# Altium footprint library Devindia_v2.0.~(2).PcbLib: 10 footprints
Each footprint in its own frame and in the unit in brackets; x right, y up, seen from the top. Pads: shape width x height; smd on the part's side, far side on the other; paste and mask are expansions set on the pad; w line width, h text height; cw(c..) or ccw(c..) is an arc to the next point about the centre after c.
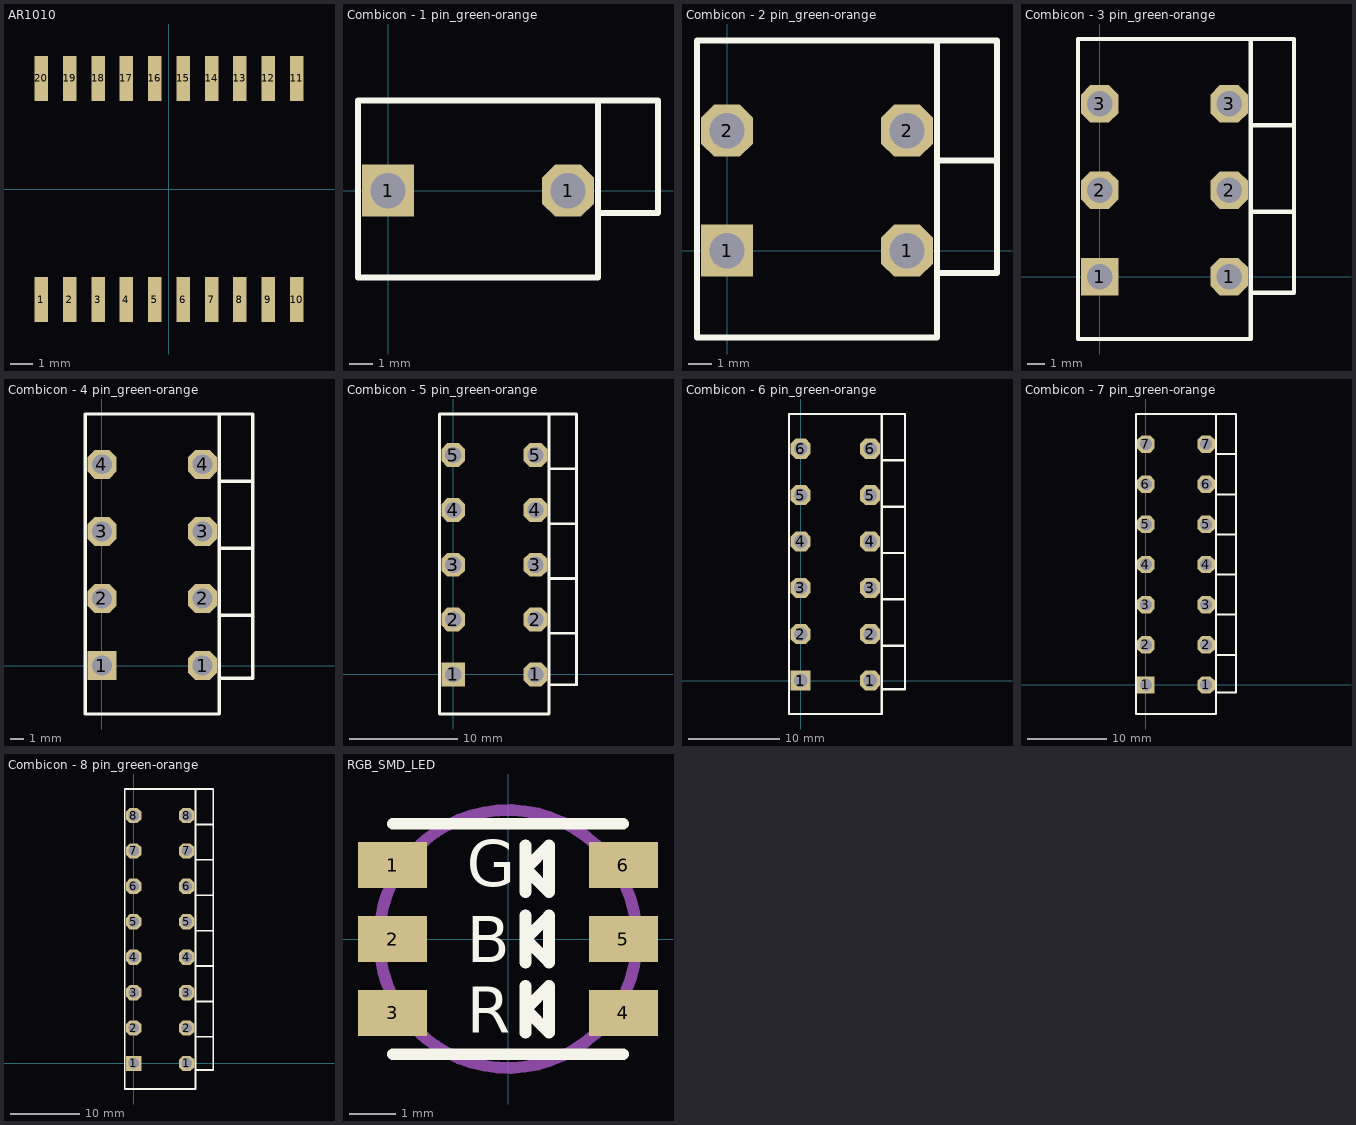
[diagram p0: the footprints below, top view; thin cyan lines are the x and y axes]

## AR1010 [mm]
pads (20):
  rect 0.6x2 smd: 1(-5.715,-4.95) 2(-4.445,-4.95) 3(-3.175,-4.95) 4(-1.905,-4.95) 5(-0.635,-4.95) 6(0.635,-4.95) 7(1.905,-4.95) 8(3.175,-4.95) 9(4.445,-4.95) 10(5.715,-4.95) 11(5.715,4.95) 12(4.445,4.95) 13(3.175,4.95) 14(1.905,4.95) 15(0.635,4.95) 16(-0.635,4.95) 17(-1.905,4.95) 18(-3.175,4.95) 19(-4.445,4.95) 20(-5.715,4.95)
Bottom Overlay:
  circle w0.254: c-5.695,-3.115 r0.284
  lines w0.254: -6.4,-3.75 -6.4,3.75 6.4,3.75 6.4,-3.75 -6.4,-3.75
3D body: height 2.15, standoff 2.05, extent -5.969,-2.54 -5.46,-2.034
3D body: height 0.32, standoff 0, extent -5.969,-5.588 -5.461,-4.318
3D body: height 1, standoff 0.16, extent -5.969,-4.445 -5.461,-4.191
3D body: height 0.32, standoff 0, extent -5.969,-4.51 -5.461,-4.191
3D body: height 1.16, standoff 0.84, extent -5.969,-4.445 -5.461,-4.126
3D body: height 1.16, standoff 0.84, extent -5.969,-4.318 -5.461,-3.175
3D body: height 0.32, standoff 0, extent -4.699,-5.588 -4.191,-4.318
3D body: height 1, standoff 0.16, extent -4.699,-4.445 -4.191,-4.191
3D body: height 0.32, standoff 0, extent -4.699,-4.51 -4.191,-4.191
3D body: height 1.16, standoff 0.84, extent -4.699,-4.445 -4.191,-4.126
3D body: height 1.16, standoff 0.84, extent -4.699,-4.318 -4.191,-3.175
3D body: height 0.32, standoff 0, extent -3.429,-5.588 -2.921,-4.318
3D body: height 1, standoff 0.16, extent -3.429,-4.445 -2.921,-4.191
3D body: height 0.32, standoff 0, extent -3.429,-4.51 -2.921,-4.191
3D body: height 1.16, standoff 0.84, extent -3.429,-4.445 -2.921,-4.126
3D body: height 1.16, standoff 0.84, extent -3.429,-4.318 -2.921,-3.175
3D body: height 0.32, standoff 0, extent -2.159,-5.588 -1.651,-4.318
3D body: height 1, standoff 0.16, extent -2.159,-4.445 -1.651,-4.191
3D body: height 0.32, standoff 0, extent -2.159,-4.51 -1.651,-4.191
3D body: height 1.16, standoff 0.84, extent -2.159,-4.445 -1.651,-4.126
3D body: height 1.16, standoff 0.84, extent -2.159,-4.318 -1.651,-3.175
3D body: height 0.32, standoff 0, extent -0.889,-5.588 -0.381,-4.318
3D body: height 1, standoff 0.16, extent -0.889,-4.445 -0.381,-4.191
3D body: height 0.32, standoff 0, extent -0.889,-4.51 -0.381,-4.191
3D body: height 1.16, standoff 0.84, extent -0.889,-4.445 -0.381,-4.126
3D body: height 1.16, standoff 0.84, extent -0.889,-4.318 -0.381,-3.175
3D body: height 0.32, standoff 0, extent 0.381,-5.588 0.889,-4.318
3D body: height 1, standoff 0.16, extent 0.381,-4.445 0.889,-4.191
3D body: height 0.32, standoff 0, extent 0.381,-4.51 0.889,-4.191
3D body: height 1.16, standoff 0.84, extent 0.381,-4.445 0.889,-4.126
3D body: height 1.16, standoff 0.84, extent 0.381,-4.318 0.889,-3.175
3D body: height 0.32, standoff 0, extent 1.651,-5.588 2.159,-4.318
3D body: height 1, standoff 0.16, extent 1.651,-4.445 2.159,-4.191
3D body: height 0.32, standoff 0, extent 1.651,-4.51 2.159,-4.191
3D body: height 1.16, standoff 0.84, extent 1.651,-4.445 2.159,-4.126
3D body: height 1.16, standoff 0.84, extent 1.651,-4.318 2.159,-3.175
3D body: height 0.32, standoff 0, extent 2.921,-5.588 3.429,-4.318
3D body: height 1, standoff 0.16, extent 2.921,-4.445 3.429,-4.191
3D body: height 0.32, standoff 0, extent 2.921,-4.51 3.429,-4.191
3D body: height 1.16, standoff 0.84, extent 2.921,-4.445 3.429,-4.126
3D body: height 1.16, standoff 0.84, extent 2.921,-4.318 3.429,-3.175
3D body: height 0.32, standoff 0, extent 4.191,-5.588 4.699,-4.318
3D body: height 1, standoff 0.16, extent 4.191,-4.445 4.699,-4.191
3D body: height 0.32, standoff 0, extent 4.191,-4.51 4.699,-4.191
3D body: height 1.16, standoff 0.84, extent 4.191,-4.445 4.699,-4.126
3D body: height 1.16, standoff 0.84, extent 4.191,-4.318 4.699,-3.175
3D body: height 0.32, standoff 0, extent 5.461,-5.588 5.969,-4.318
3D body: height 1, standoff 0.16, extent 5.461,-4.445 5.969,-4.191
3D body: height 0.32, standoff 0, extent 5.461,-4.51 5.969,-4.191
3D body: height 1.16, standoff 0.84, extent 5.461,-4.445 5.969,-4.126
3D body: height 1.16, standoff 0.84, extent 5.461,-4.318 5.969,-3.175
3D body: height 0.32, standoff 0, extent 5.461,4.318 5.969,5.588
3D body: height 1, standoff 0.16, extent 5.461,4.191 5.969,4.445
3D body: height 0.32, standoff 0, extent 5.461,4.191 5.969,4.51
3D body: height 1.16, standoff 0.84, extent 5.461,4.126 5.969,4.445
3D body: height 1.16, standoff 0.84, extent 5.461,3.175 5.969,4.318
3D body: height 0.32, standoff 0, extent 4.191,4.318 4.699,5.588
3D body: height 1, standoff 0.16, extent 4.191,4.191 4.699,4.445
3D body: height 0.32, standoff 0, extent 4.191,4.191 4.699,4.51
3D body: height 1.16, standoff 0.84, extent 4.191,4.126 4.699,4.445
3D body: height 1.16, standoff 0.84, extent 4.191,3.175 4.699,4.318
3D body: height 0.32, standoff 0, extent 2.921,4.318 3.429,5.588
3D body: height 1, standoff 0.16, extent 2.921,4.191 3.429,4.445
3D body: height 0.32, standoff 0, extent 2.921,4.191 3.429,4.51
3D body: height 1.16, standoff 0.84, extent 2.921,4.126 3.429,4.445
3D body: height 1.16, standoff 0.84, extent 2.921,3.175 3.429,4.318
3D body: height 0.32, standoff 0, extent 1.651,4.318 2.159,5.588
3D body: height 1, standoff 0.16, extent 1.651,4.191 2.159,4.445
3D body: height 0.32, standoff 0, extent 1.651,4.191 2.159,4.51
3D body: height 1.16, standoff 0.84, extent 1.651,4.126 2.159,4.445
3D body: height 1.16, standoff 0.84, extent 1.651,3.175 2.159,4.318
3D body: height 0.32, standoff 0, extent 0.381,4.318 0.889,5.588
3D body: height 1, standoff 0.16, extent 0.381,4.191 0.889,4.445
3D body: height 0.32, standoff 0, extent 0.381,4.191 0.889,4.51
3D body: height 1.16, standoff 0.84, extent 0.381,4.126 0.889,4.445
3D body: height 1.16, standoff 0.84, extent 0.381,3.175 0.889,4.318
3D body: height 0.32, standoff 0, extent -0.889,4.318 -0.381,5.588
3D body: height 1, standoff 0.16, extent -0.889,4.191 -0.381,4.445
3D body: height 0.32, standoff 0, extent -0.889,4.191 -0.381,4.51
3D body: height 1.16, standoff 0.84, extent -0.889,4.126 -0.381,4.445
3D body: height 1.16, standoff 0.84, extent -0.889,3.175 -0.381,4.318
3D body: height 0.32, standoff 0, extent -2.159,4.318 -1.651,5.588
3D body: height 1, standoff 0.16, extent -2.159,4.191 -1.651,4.445
3D body: height 0.32, standoff 0, extent -2.159,4.191 -1.651,4.51
3D body: height 1.16, standoff 0.84, extent -2.159,4.126 -1.651,4.445
3D body: height 1.16, standoff 0.84, extent -2.159,3.175 -1.651,4.318
3D body: height 0.32, standoff 0, extent -3.429,4.318 -2.921,5.588
3D body: height 1, standoff 0.16, extent -3.429,4.191 -2.921,4.445
3D body: height 0.32, standoff 0, extent -3.429,4.191 -2.921,4.51
3D body: height 1.16, standoff 0.84, extent -3.429,4.126 -2.921,4.445
3D body: height 1.16, standoff 0.84, extent -3.429,3.175 -2.921,4.318
3D body: height 0.32, standoff 0, extent -4.699,4.318 -4.191,5.588
3D body: height 1, standoff 0.16, extent -4.699,4.191 -4.191,4.445
3D body: height 1.16, standoff 0.84, extent -4.699,3.175 -4.191,4.318
3D body: height 0.32, standoff 0, extent -4.699,4.191 -4.191,4.51
3D body: height 1.16, standoff 0.84, extent -4.699,4.126 -4.191,4.445
3D body: height 0.32, standoff 0, extent -5.969,4.318 -5.461,5.588
3D body: height 1, standoff 0.16, extent -5.969,4.191 -5.461,4.445
3D body: height 1.16, standoff 0.84, extent -5.969,3.175 -5.461,4.318
3D body: height 0.32, standoff 0, extent -5.969,4.191 -5.461,4.51
3D body: height 1.16, standoff 0.84, extent -5.969,4.126 -5.461,4.445
3D body: height 1.18, standoff 0.1, extent -6.35,-3.81 6.35,3.81
3D body: height 2.05, standoff 1.05, extent -6.35,-3.175 6.35,3.175

## Combicon - 1 pin_green-orange [mm]
pads (2):
  rect 2.2x2.2 hole 1.5: 1(0,0)
  oct 2.2x2.2 hole 1.5: 1(7.62,0)
Top Overlay:
  lines w0.254: 8.956,-0.95 11.43,-0.95 11.43,3.81 8.89,3.81 ; 8.89,3.81 -1.27,3.81 -1.27,0.07 -1.27,-3.67 8.89,-3.67 8.89,3.81
3D body: height 13.66, standoff 7.75, extent 8.89,-1.016 11.43,3.81
3D body: height 13.5, standoff 13, extent 5.969,-1.503 8.864,1.397
3D body: height 13, standoff 0, extent -1.27,-3.683 8.89,3.81

## Combicon - 2 pin_green-orange [mm]
pads (4):
  rect 2.2x2.2 hole 1.5: 1(0,0)
  oct 2.2x2.2 hole 1.5: 1(7.62,0) 2(0,5.08) 2(7.62,5.08)
Top Overlay:
  lines w0.254: 8.956,-0.95 11.43,-0.95 11.43,3.81 ; 8.89,3.81 8.89,8.89 ; 8.89,3.81 8.89,-3.67 -1.27,-3.67 -1.27,0.07 -1.27,8.89 8.89,8.89 ; 8.89,3.81 11.43,3.81 ; 8.89,8.89 11.43,8.89 11.43,3.81
3D body: height 13, standoff 0, extent -1.27,-3.683 8.89,8.89
3D body: height 13.5, standoff 13, extent 5.969,-1.503 8.864,1.397
3D body: height 13.5, standoff 13, extent 5.969,3.577 8.864,6.477
3D body: height 13.66, standoff 7.75, extent 8.89,4.064 11.43,8.89
3D body: height 13.66, standoff 7.75, extent 8.89,-1.016 11.43,3.81

## Combicon - 3 pin_green-orange [mm]
pads (6):
  rect 2.2x2.2 hole 1.5: 1(0,0)
  oct 2.2x2.2 hole 1.5: 1(7.62,0) 2(0,5.08) 2(7.62,5.08) 3(0,10.16) 3(7.62,10.16)
Top Overlay:
  lines w0.254: 8.89,8.89 11.43,8.89 ; 8.956,-0.95 11.43,-0.95 11.43,3.81 ; 8.89,3.81 8.89,13.97 ; 8.89,3.81 8.89,-3.67 -1.27,-3.67 -1.27,0.07 -1.27,13.97 8.89,13.97 ; 8.89,3.81 11.43,3.81 ; 8.89,13.97 11.43,13.97 11.43,8.89 ; 11.43,3.81 11.43,8.89
3D body: height 13, standoff 0, extent -1.27,-3.683 8.89,13.97
3D body: height 13.5, standoff 13, extent 5.969,-1.503 8.864,1.397
3D body: height 13.5, standoff 13, extent 5.969,3.577 8.864,6.477
3D body: height 13.5, standoff 13, extent 5.969,8.657 8.864,11.557
3D body: height 13.66, standoff 7.75, extent 8.89,9.144 11.43,13.97
3D body: height 13.66, standoff 7.75, extent 8.89,4.064 11.43,8.89
3D body: height 13.66, standoff 7.75, extent 8.89,-1.016 11.43,3.81

## Combicon - 4 pin_green-orange [mm]
pads (8):
  rect 2.2x2.2 hole 1.5: 1(0,0)
  oct 2.2x2.2 hole 1.5: 1(7.62,0) 2(0,5.08) 2(7.62,5.08) 3(0,10.16) 3(7.62,10.16) 4(0,15.24) 4(7.62,15.24)
Top Overlay:
  lines w0.254: 8.89,8.89 11.43,8.89 ; 8.89,13.97 11.43,13.97 ; 8.956,-0.95 11.43,-0.95 11.43,3.81 ; 8.89,3.81 8.89,19.05 ; 8.89,3.81 8.89,-3.67 -1.27,-3.67 -1.27,0.07 -1.27,19.05 8.89,19.05 ; 8.89,3.81 11.43,3.81 ; 8.89,19.05 11.43,19.05 11.43,13.97 ; 11.43,3.81 11.43,8.89 ; 11.43,8.89 11.43,13.97
3D body: height 13, standoff 0, extent -1.27,-3.683 8.89,19.05
3D body: height 13.5, standoff 13, extent 5.969,-1.503 8.864,1.397
3D body: height 13.5, standoff 13, extent 5.969,3.577 8.864,6.477
3D body: height 13.5, standoff 13, extent 5.969,8.657 8.864,11.557
3D body: height 13.5, standoff 13, extent 5.969,13.737 8.864,16.637
3D body: height 13.66, standoff 7.75, extent 8.89,14.224 11.43,19.05
3D body: height 13.66, standoff 7.75, extent 8.89,9.144 11.43,13.97
3D body: height 13.66, standoff 7.75, extent 8.89,4.064 11.43,8.89
3D body: height 13.66, standoff 7.75, extent 8.89,-1.016 11.43,3.81

## Combicon - 5 pin_green-orange [mm]
pads (10):
  rect 2.2x2.2 hole 1.5: 1(0,0)
  oct 2.2x2.2 hole 1.5: 1(7.62,0) 2(0,5.08) 2(7.62,5.08) 3(0,10.16) 3(7.62,10.16) 4(0,15.24) 4(7.62,15.24) 5(0,20.32) 5(7.62,20.32)
Top Overlay:
  lines w0.254: 8.89,8.89 11.43,8.89 ; 8.89,13.97 11.43,13.97 ; 8.89,19.05 11.43,19.05 ; 8.956,-0.95 11.43,-0.95 11.43,3.81 ; 8.89,3.81 11.43,3.81 ; 8.89,3.81 8.89,-3.67 -1.27,-3.67 -1.27,0.07 -1.27,24.13 8.89,24.13 ; 8.89,3.81 8.89,24.13 ; 8.89,24.13 11.43,24.13 11.43,19.05 ; 11.43,3.81 11.43,8.89 ; 11.43,8.89 11.43,13.97 ; 11.43,13.97 11.43,19.05
3D body: height 13.66, standoff 7.75, extent 8.89,-1.016 11.43,3.81
3D body: height 13.66, standoff 7.75, extent 8.89,4.064 11.43,8.89
3D body: height 13.66, standoff 7.75, extent 8.89,9.144 11.43,13.97
3D body: height 13.66, standoff 7.75, extent 8.89,14.224 11.43,19.05
3D body: height 13.66, standoff 7.75, extent 8.89,19.304 11.43,24.13
3D body: height 13.5, standoff 13, extent 5.969,18.817 8.864,21.717
3D body: height 13.5, standoff 13, extent 5.969,13.737 8.864,16.637
3D body: height 13.5, standoff 13, extent 5.969,8.657 8.864,11.557
3D body: height 13.5, standoff 13, extent 5.969,3.577 8.864,6.477
3D body: height 13.5, standoff 13, extent 5.969,-1.503 8.864,1.397
3D body: height 13, standoff 0, extent -1.27,-3.683 8.89,24.13

## Combicon - 6 pin_green-orange [mm]
pads (12):
  rect 2.2x2.2 hole 1.5: 1(0,0)
  oct 2.2x2.2 hole 1.5: 1(7.62,0) 2(0,5.08) 2(7.62,5.08) 3(0,10.16) 3(7.62,10.16) 4(0,15.24) 4(7.62,15.24) 5(0,20.32) 5(7.62,20.32) 6(0,25.4) 6(7.62,25.4)
Top Overlay:
  lines w0.254: 8.89,8.89 11.43,8.89 ; 8.89,13.97 11.43,13.97 ; 8.89,19.05 11.43,19.05 ; 8.89,24.13 11.43,24.13 ; 8.956,-0.95 11.43,-0.95 11.43,3.81 ; 8.89,3.81 8.89,29.21 ; 8.89,3.81 8.89,-3.67 -1.27,-3.67 -1.27,0.07 -1.27,29.21 8.89,29.21 ; 8.89,3.81 11.43,3.81 ; 8.89,29.21 11.43,29.21 11.43,24.13 ; 11.43,3.81 11.43,8.89 ; 11.43,8.89 11.43,13.97 ; 11.43,13.97 11.43,19.05 ; 11.43,19.05 11.43,24.13
3D body: height 13, standoff 0, extent -1.27,-3.683 8.89,29.21
3D body: height 13.5, standoff 13, extent 5.969,-1.503 8.864,1.397
3D body: height 13.5, standoff 13, extent 5.969,3.577 8.864,6.477
3D body: height 13.5, standoff 13, extent 5.969,8.657 8.864,11.557
3D body: height 13.5, standoff 13, extent 5.969,13.737 8.864,16.637
3D body: height 13.5, standoff 13, extent 5.969,18.817 8.864,21.717
3D body: height 13.5, standoff 13, extent 5.969,23.897 8.864,26.797
3D body: height 13.66, standoff 7.75, extent 8.89,24.384 11.43,29.21
3D body: height 13.66, standoff 7.75, extent 8.89,19.304 11.43,24.13
3D body: height 13.66, standoff 7.75, extent 8.89,14.224 11.43,19.05
3D body: height 13.66, standoff 7.75, extent 8.89,9.144 11.43,13.97
3D body: height 13.66, standoff 7.75, extent 8.89,4.064 11.43,8.89
3D body: height 13.66, standoff 7.75, extent 8.89,-1.016 11.43,3.81

## Combicon - 7 pin_green-orange [mm]
pads (14):
  rect 2.2x2.2 hole 1.5: 1(0,0)
  oct 2.2x2.2 hole 1.5: 1(7.62,0) 2(0,5.08) 2(7.62,5.08) 3(0,10.16) 3(7.62,10.16) 4(0,15.24) 4(7.62,15.24) 5(0,20.32) 5(7.62,20.32) 6(0,25.4) 6(7.62,25.4) 7(0,30.48) 7(7.62,30.48)
Top Overlay:
  lines w0.254: 8.89,8.89 11.43,8.89 ; 8.89,13.97 11.43,13.97 ; 8.89,19.05 11.43,19.05 ; 8.89,24.13 11.43,24.13 ; 8.89,29.21 11.43,29.21 ; 8.956,-0.95 11.43,-0.95 11.43,3.81 ; 8.89,3.81 8.89,34.29 ; 8.89,3.81 8.89,-3.67 -1.27,-3.67 -1.27,0.07 -1.27,34.29 8.89,34.29 ; 8.89,3.81 11.43,3.81 ; 8.89,34.29 11.43,34.29 ; 8.89,34.29 11.43,34.29 ; 11.43,3.81 11.43,8.89 ; 11.43,8.89 11.43,13.97 ; 11.43,13.97 11.43,19.05 ; 11.43,19.05 11.43,24.13 ; 11.43,24.13 11.43,29.21 ; 11.43,29.21 11.43,34.29
3D body: height 13, standoff 0, extent -1.27,-3.683 8.89,34.29
3D body: height 13.5, standoff 13, extent 5.969,-1.503 8.864,1.397
3D body: height 13.5, standoff 13, extent 5.969,3.577 8.864,6.477
3D body: height 13.5, standoff 13, extent 5.969,8.657 8.864,11.557
3D body: height 13.5, standoff 13, extent 5.969,13.737 8.864,16.637
3D body: height 13.5, standoff 13, extent 5.969,18.817 8.864,21.717
3D body: height 13.5, standoff 13, extent 5.969,23.897 8.864,26.797
3D body: height 13.5, standoff 13, extent 5.969,28.977 8.864,31.877
3D body: height 13.66, standoff 7.75, extent 9.017,29.464 11.557,34.29
3D body: height 13.66, standoff 7.75, extent 8.89,24.384 11.43,29.21
3D body: height 13.66, standoff 7.75, extent 8.89,19.304 11.43,24.13
3D body: height 13.66, standoff 7.75, extent 8.89,14.224 11.43,19.05
3D body: height 13.66, standoff 7.75, extent 8.89,9.144 11.43,13.97
3D body: height 13.66, standoff 7.75, extent 8.89,4.064 11.43,8.89
3D body: height 13.66, standoff 7.75, extent 8.89,-1.016 11.43,3.81

## Combicon - 8 pin_green-orange [mm]
pads (16):
  rect 2.2x2.2 hole 1.5: 1(0,0)
  oct 2.2x2.2 hole 1.5: 1(7.62,0) 2(0,5.08) 2(7.62,5.08) 3(0,10.16) 3(7.62,10.16) 4(0,15.24) 4(7.62,15.24) 5(0,20.32) 5(7.62,20.32) 6(0,25.4) 6(7.62,25.4) 7(0,30.48) 7(7.62,30.48) 8(0,35.56) 8(7.62,35.56)
Top Overlay:
  lines w0.254: 8.89,8.89 11.43,8.89 ; 8.89,13.97 11.43,13.97 ; 8.89,19.05 11.43,19.05 ; 8.89,24.13 11.43,24.13 ; 8.89,29.21 11.43,29.21 ; 8.89,34.29 11.43,34.29 ; 8.956,-0.95 11.43,-0.95 11.43,3.81 ; 8.89,3.81 11.43,3.81 ; 8.89,3.81 8.89,-3.67 -1.27,-3.67 -1.27,0.07 -1.27,39.37 8.89,39.37 ; 8.89,3.81 8.89,39.37 ; 8.89,39.37 11.43,39.37 11.43,34.29 ; 11.43,3.81 11.43,8.89 ; 11.43,8.89 11.43,13.97 ; 11.43,13.97 11.43,19.05 ; 11.43,19.05 11.43,24.13 ; 11.43,24.13 11.43,29.21 ; 11.43,29.21 11.43,34.29
3D body: height 13.66, standoff 7.75, extent 8.89,-1.016 11.43,3.81
3D body: height 13.66, standoff 7.75, extent 8.89,4.064 11.43,8.89
3D body: height 13.66, standoff 7.75, extent 8.89,9.144 11.43,13.97
3D body: height 13.66, standoff 7.75, extent 8.89,14.224 11.43,19.05
3D body: height 13.66, standoff 7.75, extent 8.89,19.304 11.43,24.13
3D body: height 13.66, standoff 7.75, extent 8.89,24.384 11.43,29.21
3D body: height 13.66, standoff 7.75, extent 9.017,29.464 11.557,34.29
3D body: height 13.66, standoff 7.75, extent 8.89,34.544 11.43,39.37
3D body: height 13.5, standoff 13, extent 5.969,34.057 8.864,36.957
3D body: height 13.5, standoff 13, extent 5.969,28.977 8.864,31.877
3D body: height 13.5, standoff 13, extent 5.969,23.897 8.864,26.797
3D body: height 13.5, standoff 13, extent 5.969,18.817 8.864,21.717
3D body: height 13.5, standoff 13, extent 5.969,13.737 8.864,16.637
3D body: height 13.5, standoff 13, extent 5.969,8.657 8.864,11.557
3D body: height 13.5, standoff 13, extent 5.969,3.577 8.864,6.477
3D body: height 13.5, standoff 13, extent 5.969,-1.503 8.864,1.397
3D body: height 13, standoff 0, extent -1.27,-3.683 8.89,39.37

## RGB_SMD_LED [mm]
pads (6):
  rect 1.5x1 all layers, no hole: 1(-2.5,1.6) 2(-2.5,0) 3(-2.5,-1.6) 4(2.5,-1.6) 5(2.5,0) 6(2.5,1.6)
Top Overlay:
  lines w0.254: -2.5,-2.5 2.5,-2.5 ; -2.5,2.5 2.5,2.5 ; 0.381,-2.032 0.381,-1.016 0.381,-1.524 ; 0.381,-0.508 0.381,0.508 0.381,0 ; 0.381,1.016 0.381,2.032 0.381,1.524 ; 0.381,-1.524 0.889,-1.016 0.889,-2.032 0.381,-1.524 ; 0.381,0 0.889,0.508 0.889,-0.508 0.381,0 ; 0.381,1.524 0.889,2.032 0.889,1.016 0.381,1.524
  text "G" at -0.889,1.143 h1
  text "B" at -0.889,-0.508 h1
  text "R" at -0.889,-2.032 h1
Mechanical 1:
  circle w0.254: c0,0 r2.794
3D body: height 1.7, standoff 1.68, extent 0.381,-2.794 2.159,-0.762
3D body: height 1.7, standoff 1.68, extent 0.254,0.762 2.159,2.794
3D body: height 1.7, standoff 1.68, extent -2.286,1.27 -0.254,2.794
3D body: height 1.68, standoff 0.2, extent -3.429,-3.175 3.429,3.175
3D body: height 0.2, standoff 0, extent -3.175,1.27 -1.905,1.905
3D body: height 0.2, standoff 0, extent -3.175,-0.33 -1.905,0.305
3D body: height 0.2, standoff 0, extent -3.175,-1.93 -1.905,-1.295
3D body: height 0.2, standoff 0, extent 1.825,-1.93 3.095,-1.295
3D body: height 0.2, standoff 0, extent 1.825,-0.33 3.095,0.305
3D body: height 0.2, standoff 0, extent 1.825,1.27 3.095,1.905
3D body: height 1.7, standoff 1.68, extent -2.794,-0.381 -1.524,0.381
3D body: height 1.7, standoff 1.68, extent -0.889,-0.889 2.667,0.889
3D body: height 1.7, standoff 1.68, extent -2.286,-2.794 -0.254,-1.27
